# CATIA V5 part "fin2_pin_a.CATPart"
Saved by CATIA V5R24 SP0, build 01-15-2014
Part number: Pin A
Bounding box of the stored display mesh (mm): x -1.478 to 1.478, y -1.498 to 1.498, z -7.5 to 0
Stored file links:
  G:\내 드라이브\04_WORK\00_LECTURE\CAD2020\exam\fin2_pin_a.CATPart
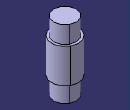
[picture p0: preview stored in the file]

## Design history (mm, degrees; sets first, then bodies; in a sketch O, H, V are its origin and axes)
Body1 (main body)
  Sketch1 on yz-plane, origin (0, 0, 0), H (0, 1, 0), V (0, 0, 1)
    axis line L1 (0, 33.1849) -> (0, -66.3699)
    point P1 (0, 33.1849)
    line L2 (0, 0) -> (-1.25, 0)
    line L3 (-1.25, 0) -> (-1.25, -1.875)
    line L4 (-1.25, -1.875) -> (-1.5, -1.875)
    line L5 (-1.5, -1.875) -> (-1.5, -5.625)
    line L6 (-1.5, -5.625) -> (-1.25, -5.625)
    point P7 (-1.25, -5.625)
    line L7 (-1.25, -5.625) -> (-1.25, -7.5)
    line L8 (-1.25, -7.5) -> (0, -7.5)
    point P9 (0, -7.5)
    length L7 = 1.875
    distance L4 L2 = 1.875
    distance L5 L1 = 1.5
    distance L3 L1 = 1.25
    distance L8 L2 = 7.5
    coincidence: P1 V, P7 L3, P9 V
    vertical: L1 V, L3 V, L5 V, L7 V
    horizontal: L2 H, L4 H, L8 H, L6 H
  Shaft1: profile Sketch1, axis Sketch1.L1, angle 360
